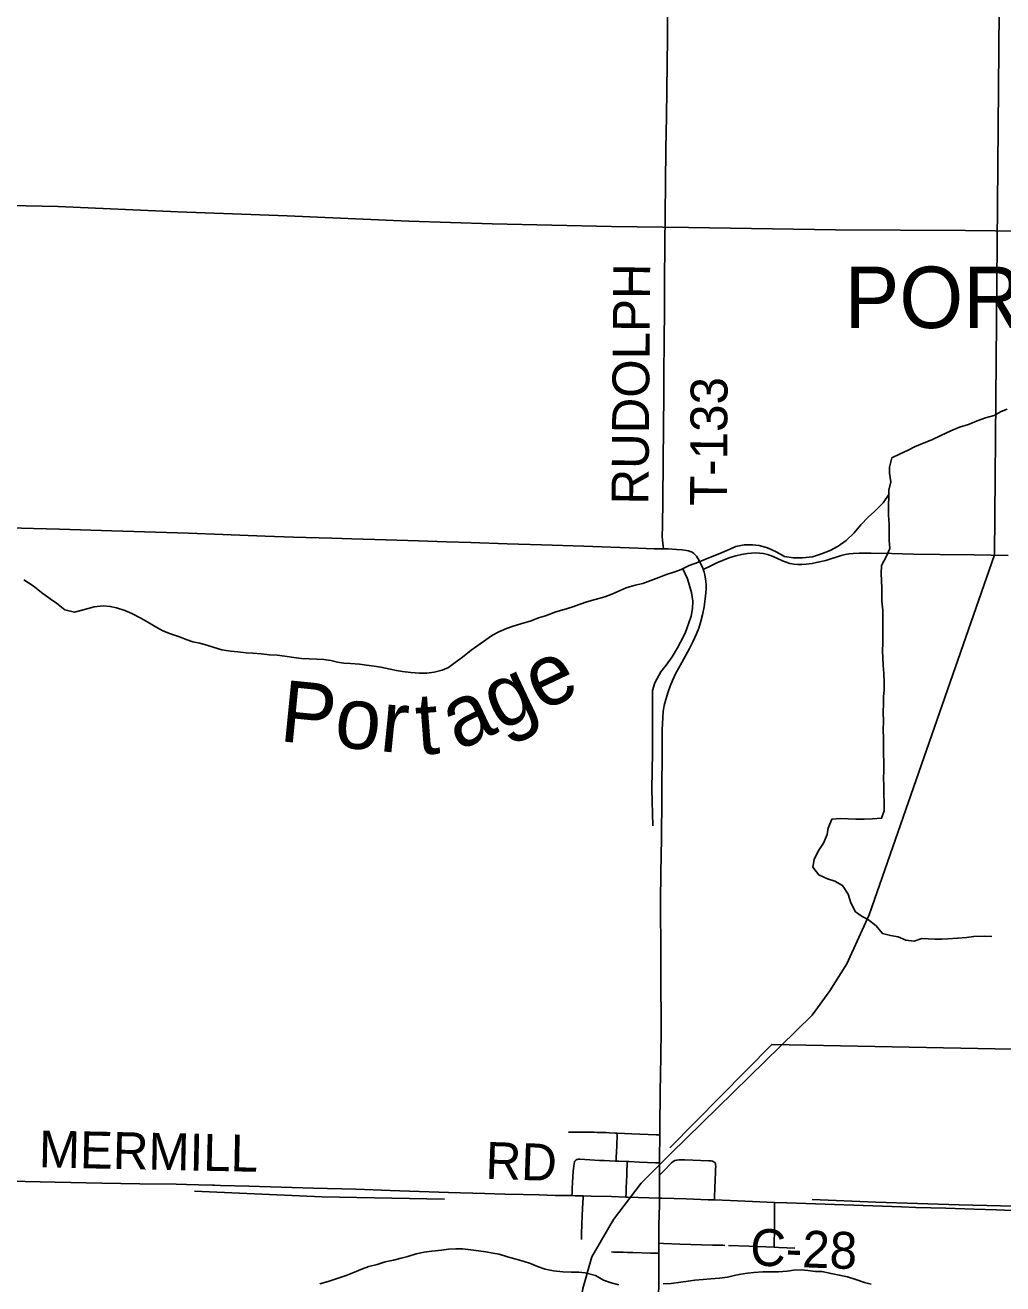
# Model space of a CAD drawing. Extents: x 0 to 680, y 0 to 834.
# Drawn here: x 266.4 to 324.2, y 148.8 to 223.2 of the extents above; entities that cross this region are included whole.
import ezdxf

# ---------------------------------------------------------------- set-up
doc = ezdxf.new("R2010")
doc.units = 0
for name, color, linetype in [('GM_X_Corporation_Text', 7, 'Continuous'), ('GM_X_County_Road', 7, 'Continuous'), ('GM_X_County_Road_Text', 7, 'Continuous'), ('GM_X_Major_River', 7, 'Continuous'), ('GM_X_Major_River_Text', 7, 'Continuous'), ('GM_X_Minor_River', 7, 'Continuous'), ('GM_X_Rail_Line', 7, 'Continuous'), ('GM_X_Township_Road', 7, 'Continuous'), ('GM_X_Township_Road_Text', 7, 'Continuous')]:
    doc.layers.add(name, color=color, linetype=linetype)

msp = doc.modelspace()

# ---------------------------------------------------------------- linework, layer by layer
at = {"layer": 'GM_X_County_Road'}
for points in [[(264.846, 154.87), (266.381, 154.814), (268.171, 154.759), (270.915, 154.707), (273.182, 154.673), (275.33, 154.639), (275.926, 154.624), (276.642, 154.609), (277.477, 154.592), (277.596, 154.589), (277.954, 154.574), (279.625, 154.533), (283.443, 154.417), (285.948, 154.342), (287.976, 154.27), (291.434, 154.148), (293.582, 154.09), (294.774, 154.056), (295.847, 154.037), (296.8, 154.016), (297.749, 153.986), (298.739, 153.968)], [(298.739, 153.968), (298.932, 153.964), (299.403, 153.953)], [(299.403, 153.953), (299.886, 153.941), (301.079, 153.913), (301.939, 153.881)], [(301.939, 153.881), (302.033, 153.878), (303.918, 153.82)], [(303.918, 153.82), (304.06, 153.816), (305.491, 153.773), (306.802, 153.725), (307.177, 153.712)], [(307.177, 153.712), (308.113, 153.681), (309.425, 153.617), (310.737, 153.565)], [(310.737, 153.565), (311.451, 153.537), (318.25, 153.307), (319.084, 153.267), (320.873, 153.221), (322.543, 153.165), (323.855, 153.121), (324.809, 153.093), (325.764, 153.069), (327.195, 153.029), (327.935, 153.016), (328.508, 153.006), (329.581, 152.976), (331.728, 152.957), (332.444, 152.957), (334.712, 152.923), (336.263, 152.896), (338.053, 152.879), (339.485, 152.854), (341.274, 152.836), (342.032, 152.832)]]:
    msp.add_lwpolyline(points, dxfattribs=at)
at = {"layer": 'GM_X_Major_River'}
for points in [[(324.495, 200.502), (324.13, 200.357), (323.721, 200.125), (323.211, 199.981), (322.729, 199.807), (322.204, 199.605), (321.679, 199.431), (321.169, 199.229), (320.571, 198.953), (320.031, 198.692), (319.578, 198.504), (319.009, 198.272), (318.63, 198.084), (318.163, 197.867)], [(318.163, 197.867), (317.667, 197.62), (317.534, 197.081), (317.533, 196.716), (317.604, 196.206), (317.486, 195.71), (317.485, 195.448)], [(317.485, 195.448), (317.148, 194.953), (316.637, 194.458), (316.272, 194.109), (315.833, 193.659), (315.438, 193.193), (314.971, 192.728), (314.489, 192.394), (314.022, 192.133), (313.511, 191.945), (312.971, 191.757), (312.388, 191.7), (311.849, 191.702), (311.325, 191.791), (310.831, 192.055), (310.307, 192.304), (309.812, 192.437), (309.433, 192.482), (308.938, 192.483), (308.442, 192.368), (308.048, 192.209), (307.64, 192.02), (307.188, 191.847), (306.75, 191.673), (306.225, 191.441), (305.67, 191.253), (305.203, 191.007), (304.839, 190.876), (304.285, 190.703), (303.876, 190.544), (303.409, 190.37), (302.943, 190.197), (302.491, 190.096), (301.951, 189.922), (301.586, 189.778), (301.105, 189.56), (300.682, 189.401), (300.113, 189.242), (299.632, 189.113), (299.224, 188.968), (298.728, 188.794), (298.29, 188.65), (297.794, 188.506), (297.182, 188.274), (296.759, 188.159), (296.321, 187.97), (295.723, 187.797), (295.271, 187.667), (294.877, 187.522), (294.425, 187.32), (294.046, 187.131), (293.651, 186.855), (293.17, 186.521), (292.775, 186.245), (292.264, 185.824), (291.826, 185.519), (291.446, 185.214), (291.067, 185.069), (290.586, 184.939), (290.163, 184.882), (289.726, 184.883), (289.216, 184.929), (288.721, 184.974), (288.357, 185.033), (287.979, 185.122), (287.44, 185.24), (287.047, 185.3), (286.581, 185.359), (286.173, 185.419), (285.648, 185.45), (285.241, 185.48), (284.877, 185.54), (284.483, 185.628), (284.061, 185.688), (283.653, 185.718), (283.202, 185.734), (282.736, 185.75), (282.284, 185.81), (281.745, 185.884), (281.294, 185.944), (280.842, 185.974), (280.347, 186.02), (279.866, 186.065), (279.459, 186.095), (278.963, 186.141), (278.541, 186.186), (278.031, 186.26), (277.58, 186.393), (277.202, 186.51), (276.721, 186.658), (276.3, 186.742), (275.921, 186.879), (275.513, 187.041), (274.989, 187.203), (274.538, 187.379), (274.044, 187.658), (273.637, 187.907), (273.229, 188.141), (272.706, 188.405), (272.284, 188.596), (271.789, 188.758)], [(271.789, 188.758), (271.425, 188.832), (271.003, 188.863), (270.478, 188.806), (270.113, 188.705), (269.676, 188.589), (269.308, 188.484), (268.729, 188.636), (268.249, 189.017), (267.872, 189.28), (267.363, 189.661), (266.869, 190.042), (266.301, 190.408)], [(301.516, 148.689), (301.065, 148.807), (300.613, 148.969), (300.133, 149.233), (299.522, 149.395), (299.158, 149.44), (298.692, 149.442), (298.197, 149.458), (297.658, 149.518), (297.163, 149.621), (296.697, 149.769), (296.289, 149.945), (295.911, 150.077), (295.358, 150.225), (294.936, 150.357), (294.441, 150.505), (294.062, 150.564), (293.655, 150.638), (293.203, 150.698), (292.766, 150.757), (292.271, 150.817), (291.878, 150.818), (291.441, 150.791), (291.018, 150.748), (290.45, 150.677), (289.998, 150.62), (289.517, 150.519), (289.036, 150.375), (288.627, 150.259), (288.19, 150.158), (287.694, 150.043), (287.213, 149.899), (286.717, 149.769), (286.353, 149.639), (285.871, 149.436), (285.39, 149.248), (284.85, 149.074), (284.325, 148.886), (283.815, 148.742)], [(316.449, 148.733), (316.056, 148.836), (315.547, 149.013), (315.052, 149.16), (314.557, 149.264), (314.076, 149.353), (313.523, 149.471), (313.144, 149.487), (312.707, 149.546), (312.314, 149.577), (311.862, 149.549), (311.483, 149.492), (310.973, 149.464), (310.536, 149.45), (310.041, 149.452), (309.502, 149.424), (309.137, 149.382), (308.744, 149.324), (308.35, 149.238), (307.942, 149.152), (307.476, 149.08), (306.966, 149.038), (306.514, 149.01), (306.004, 148.968), (305.625, 148.911), (305.188, 148.839), (304.605, 148.768), (304.138, 148.74)]]:
    msp.add_lwpolyline(points, dxfattribs=at)
at = {"layer": 'GM_X_Minor_River'}
for points in [[(245.729, 222.703), (245.676, 219.669), (245.678, 215.687), (245.626, 213.106), (247.214, 213.072), (253.915, 212.95), (258.548, 212.805), (262.03, 212.707), (264.535, 212.583), (268.338, 212.499), (275.417, 212.186), (281.885, 211.933), (289.082, 211.634), (294.021, 211.473), (301.086, 211.306), (305.632, 211.249), (314.33, 211.106), (322.037, 211.069), (325.563, 211.029), (330.269, 210.957), (332.687, 210.877), (334.85, 210.826)], [(317.485, 195.448), (317.468, 194.689), (317.481, 194.223), (317.509, 193.683), (317.507, 193.245), (317.52, 192.749), (317.548, 192.253), (317.328, 191.758), (317.049, 191.249), (317.048, 190.767), (317.061, 190.388), (317.074, 189.892), (317.087, 189.528), (317.086, 189.148), (317.128, 188.609), (317.141, 188.127), (317.138, 187.136), (317.137, 186.669), (317.12, 186.188), (317.134, 185.823), (317.161, 185.327), (317.204, 184.86), (317.217, 184.364), (317.215, 183.883), (317.185, 183.504), (317.169, 183.081), (317.167, 182.57), (317.18, 182.045), (317.164, 181.535), (317.177, 181.039), (317.174, 180.105), (317.187, 179.624), (317.2, 179.085), (317.184, 178.691), (317.197, 178.209), (317.195, 177.655), (317.209, 177.261), (317.221, 176.736), (317.06, 176.299), (316.535, 176.257), (316.025, 176.244), (315.544, 176.245), (315.078, 176.261), (314.627, 176.277), (314.117, 176.235), (313.911, 175.71), (313.837, 175.346), (313.631, 174.822), (313.309, 174.341), (313.075, 173.861), (312.986, 173.409), (313.349, 172.955), (313.858, 172.706), (314.294, 172.573), (314.76, 172.324), (315.093, 171.798), (315.237, 171.287), (315.513, 170.761), (315.905, 170.483), (316.298, 170.278), (316.734, 169.941), (317.111, 169.488), (317.592, 169.369), (318.043, 169.281), (318.508, 169.075), (318.989, 169.03), (319.441, 169.189), (319.82, 169.159), (320.213, 169.143), (320.621, 169.142), (320.986, 169.17), (321.554, 169.197), (322.093, 169.24), (322.516, 169.311), (323.171, 169.324), (323.579, 169.308)], [(305.312, 191.064), (305.581, 190.466), (305.811, 189.648), (305.897, 189.138), (305.866, 188.715), (305.792, 188.248), (305.66, 187.855), (305.439, 187.258), (305.161, 186.719), (304.985, 186.384), (304.677, 185.845), (304.311, 185.365), (304.004, 184.957), (303.638, 184.317), (303.505, 183.851), (303.516, 182.523), (303.508, 180.19), (303.472, 178.017), (303.524, 175.843)], [(331.907, 162.501), (310.564, 162.914), (304.528, 156.791)], [(276.402, 154.234), (283.933, 153.905), (291.202, 153.753)], [(312.953, 153.732), (316.726, 153.59), (321.65, 153.415), (327.375, 153.281), (332.445, 153.165)]]:
    msp.add_lwpolyline(points, dxfattribs=at)
at = {"layer": 'GM_X_Rail_Line'}
msp.add_lwpolyline([(324.019, 224.102), (323.747, 191.887), (316.336, 170.579), (315.011, 167.69), (314.008, 166.083), (312.961, 164.64), (304.58, 156.45), (302.834, 154.704), (301.197, 152.565), (299.926, 150.355), (299.392, 148.48), (299.125, 146.806), (298.837, 143.215), (298.255, 115.425), (298.139, 96.174), (297.69, 68.538), (297.562, 64.069)], dxfattribs=at)
at = {"layer": 'GM_X_Township_Road'}
for p, q in [((303.92, 155.185), (303.923, 155.901)), ((303.887, 150.566), (303.887, 151.153))]:
    msp.add_line(p, q, dxfattribs=at)
for points in [[(304.165, 192.233), (304.146, 192.388), (304.122, 192.576), (304.105, 192.748), (304.089, 192.99), (304.093, 193.588), (304.119, 195.14), (304.138, 197.408), (304.152, 199.438), (304.171, 201.348), (304.185, 202.9), (304.2, 204.213), (304.213, 206.72), (304.222, 208.152), (304.237, 210.182), (304.281, 213.882), (304.303, 215.912), (304.33, 217.822), (304.351, 219.374), (304.389, 222.478), (304.423, 225.104), (304.437, 226.775), (304.453, 229.521), (304.447, 230.956)], [(264.925, 193.506), (265.465, 193.491), (266.873, 193.452), (268.424, 193.409), (271.525, 193.303), (274.746, 193.203), (276.058, 193.164), (278.086, 193.086), (280.59, 192.993), (282.26, 192.939), (284.526, 192.868), (285.719, 192.832), (287.747, 192.78), (289.655, 192.71), (291.325, 192.662), (292.757, 192.619), (294.903, 192.543), (296.931, 192.473), (299.436, 192.388), (302.656, 192.272), (303.61, 192.24), (304.165, 192.233)], [(304.165, 192.233), (304.445, 192.23), (304.923, 192.208), (305.26, 192.185), (305.516, 192.15), (305.633, 192.126), (305.746, 192.09), (305.852, 192.035), (305.95, 191.968), (306.038, 191.888), (306.114, 191.797), (306.18, 191.697), (306.242, 191.588), (306.353, 191.373), (306.439, 191.193), (306.483, 191.097), (306.515, 191.015)], [(306.515, 191.015), (306.671, 191.091), (306.811, 191.16), (306.912, 191.212), (307.313, 191.407), (307.642, 191.549), (308.088, 191.718), (308.43, 191.825), (308.778, 191.909), (309.131, 191.967), (309.369, 191.99), (309.608, 191.997), (309.846, 191.988), (310.083, 191.958), (310.315, 191.905), (310.541, 191.829), (310.868, 191.684), (311.193, 191.533), (311.415, 191.445), (311.644, 191.378), (311.878, 191.333), (312.115, 191.311), (312.354, 191.31), (312.592, 191.325), (312.947, 191.373), (313.299, 191.441), (313.762, 191.554), (314.672, 191.841), (314.904, 191.9), (315.138, 191.944), (315.375, 191.972), (315.732, 191.991), (316.448, 191.985), (317.642, 191.96), (318.954, 191.933), (320.505, 191.899), (322.534, 191.875), (324.562, 191.838)], [(303.936, 157.565), (303.94, 158.06), (303.957, 160.083), (303.977, 161.133), (303.999, 162.204), (304.012, 163.756), (304.022, 164.591), (304.011, 166.26), (304.006, 166.855), (304.01, 167.809), (303.997, 169.241), (303.991, 170.315), (303.99, 171.39), (304.009, 173.061), (304.032, 175.09), (304.051, 177.478), (304.078, 180.701), (304.086, 181.538), (304.117, 182.255), (304.149, 182.613), (304.205, 182.969), (304.288, 183.32), (304.427, 183.78), (304.547, 184.119), (304.684, 184.452), (304.895, 184.882), (305.238, 185.513), (305.706, 186.344), (305.922, 186.768), (306.115, 187.203), (306.242, 187.536), (306.349, 187.875), (306.468, 188.335), (306.56, 188.802), (306.632, 189.273), (306.669, 189.627), (306.681, 189.863), (306.677, 190.099), (306.656, 190.334), (306.599, 190.694), (306.563, 190.865), (306.515, 191.015)], [(298.547, 157.724), (298.907, 157.72), (299.417, 157.724), (299.824, 157.719), (300.058, 157.715), (300.232, 157.712), (300.616, 157.702), (300.774, 157.696), (300.94, 157.689), (301.327, 157.669), (301.422, 157.666)], [(301.362, 156.011), (301.364, 156.164), (301.365, 156.277), (301.37, 156.508), (301.39, 156.973), (301.416, 157.521), (301.422, 157.666)], [(301.422, 157.666), (302.281, 157.633), (303.718, 157.574), (303.936, 157.565)], [(303.923, 155.901), (303.925, 156.153), (303.936, 157.565)], [(298.739, 153.968), (298.747, 154.119), (298.762, 154.39), (298.781, 154.745), (298.802, 155.084), (298.82, 155.387), (298.854, 155.741), (298.874, 155.859), (298.9, 155.973), (298.911, 155.999), (298.924, 156.026), (298.944, 156.053), (298.966, 156.071), (298.993, 156.089), (299.039, 156.107), (299.07, 156.116), (299.121, 156.122), (299.2, 156.118), (299.803, 156.083), (300.381, 156.052), (300.639, 156.042), (300.963, 156.028), (301.312, 156.015), (301.362, 156.011)], [(301.362, 156.011), (301.515, 156.005), (302.014, 155.986)], [(301.939, 153.881), (301.948, 154.151), (301.956, 154.422), (301.969, 154.799), (301.981, 155.191), (301.99, 155.448), (302.001, 155.797), (302.014, 155.986)], [(302.014, 155.986), (302.133, 155.981), (302.735, 155.958), (303.689, 155.912), (303.923, 155.901)], [(303.92, 155.185), (304.136, 155.404), (304.634, 155.909), (304.727, 155.981), (304.83, 156.038), (304.943, 156.073), (305.06, 156.091), (305.178, 156.095), (305.414, 156.089), (305.903, 156.07), (306.829, 156.035), (306.983, 156.023), (307.056, 156.004), (307.107, 155.986), (307.158, 155.957), (307.201, 155.921), (307.231, 155.863), (307.242, 155.806), (307.249, 155.681), (307.243, 155.564), (307.236, 155.404), (307.214, 154.844), (307.202, 154.466), (307.18, 153.829), (307.177, 153.712)], [(303.918, 153.82), (303.917, 154.364), (303.918, 154.959), (303.92, 155.185)], [(299.299, 151.374), (299.304, 151.699), (299.325, 152.279), (299.358, 153.224), (299.396, 153.848), (299.403, 153.953)], [(303.887, 151.153), (303.888, 152.223), (303.914, 153.416), (303.915, 153.535), (303.918, 153.82)], [(310.702, 150.917), (310.707, 151.117), (310.728, 151.942), (310.731, 153.237), (310.734, 153.354), (310.737, 153.565)], [(301.087, 150.636), (301.208, 150.631), (301.366, 150.629), (301.584, 150.621), (301.763, 150.615), (302.037, 150.606), (302.354, 150.596), (303.388, 150.562), (303.625, 150.564), (303.887, 150.566)], [(303.878, 149.202), (303.886, 149.957), (303.887, 150.566)], [(303.887, 151.153), (304.161, 151.142), (305.129, 151.103), (307.066, 151.043), (307.672, 151.028), (307.793, 151.023)], [(308.01, 151.023), (309.199, 150.981), (310.702, 150.917)], [(310.702, 150.917), (310.983, 150.905), (311.934, 150.854)], [(303.859, 146.153), (303.865, 147.81), (303.876, 149.003), (303.878, 149.202)]]:
    msp.add_lwpolyline(points, dxfattribs=at)

# ---------------------------------------------------------------- texts
at = {"layer": 'GM_X_Corporation_Text'}
msp.add_text('PORTAGE', height=3.6364, rotation=0.00001, dxfattribs=at).set_placement((314.869, 205.302))
at = {"layer": 'GM_X_County_Road_Text'}
for s, rotation, p in [('MERMILL', 358.81858, (267.184, 155.644)), ('RD', 358.04095, (293.604, 154.971)), ('C-28', 357.93981, (309.259, 149.842))]:
    msp.add_text(s, height=2.1818, rotation=rotation, dxfattribs=at).set_placement(p)
at = {"layer": 'GM_X_Major_River_Text'}
for s, height, rotation, p in [('age', 3.6383, 25.32298, (292.026, 180.268)), ('Por', 3.6382, 354.32513, (281.377, 180.866)), ('t', 3.638, 4.32486, (289.63, 180.037))]:
    msp.add_text(s, height=height, rotation=rotation, dxfattribs=at).set_placement(p)
at = {"layer": 'GM_X_Township_Road_Text'}
for s, rotation, p in [('RUDOLPH', 89.56689, (303.265, 194.851)), ('T-133', 89.71922, (307.912, 194.778))]:
    msp.add_text(s, height=2.1818, rotation=rotation, dxfattribs=at).set_placement(p)

doc.saveas('drawing.dxf')
